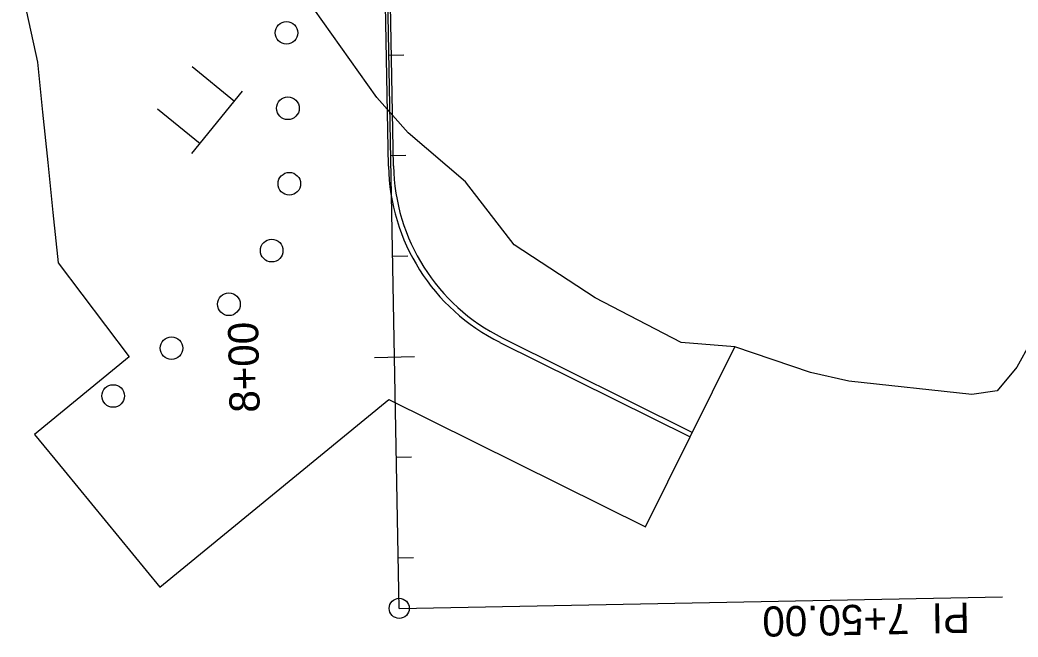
# Model space of a CAD drawing. Extents: x 1710723 to 1713003, y 548603 to 551142.
# Drawn here: x 1711666.3 to 1711864.8, y 548956.8 to 549079.5 of the extents above; entities that cross this region are included whole.
import ezdxf

# ---------------------------------------------------------------- set-up
doc = ezdxf.new("R2010")
doc.units = 0
for name, color, linetype in [('R_Horz Alg', 7, 'Continuous'), ('R_Horz Alg Annot', 7, 'Continuous'), ('R_MOT', 7, 'Continuous'), ('R_No Plot', 7, 'Continuous'), ('R_Proposed Road_Lane', 7, 'Continuous'), ('R_Striping', 7, 'Continuous')]:
    doc.layers.add(name, color=color, linetype=linetype)

msp = doc.modelspace()

# ---------------------------------------------------------------- linework, layer by layer
at = {"layer": 'R_Horz Alg'}
msp.add_line((1711741.76, 548962.46), (1711737.05, 549212.41), dxfattribs=at)
at = {"layer": 'R_Horz Alg Annot'}
for points in [[(1711742.69, 549072.5), (1711739.69, 549072.44)], [(1711743.07, 549052.5), (1711740.07, 549052.44)], [(1711743.44, 549032.5), (1711740.44, 549032.45)], [(1711736.82, 549012.38), (1711744.82, 549012.53)], [(1711744.2, 548992.51), (1711741.2, 548992.45)], [(1711744.57, 548972.51), (1711741.57, 548972.46)], [(1711741.76, 548962.46), (1711861.74, 548964.72)]]:
    msp.add_lwpolyline(points, dxfattribs=at)
msp.add_circle((1711741.76, 548962.46), 2, dxfattribs=at)
at = {"layer": 'R_MOT'}
for p, q in [((1711700.56, 549070.26), (1711709.02, 549063.36)), ((1711700.5, 549052.9), (1711710.61, 549065.3)), ((1711693.7, 549061.84), (1711702.17, 549054.94)), ((1711688.03, 549012.49), (1711669.23, 548997.07)), ((1711669.23, 548997.07), (1711675.11, 548989.89))]:
    msp.add_line(p, q, dxfattribs=at)
for points in [[(1711808.51, 549014.46), (1711797.83, 549015.34), (1711780.72, 549024.22), (1711764.61, 549034.78), (1711754.93, 549047.27), (1711743.56, 549057.03), (1711737.29, 549064.07), (1711724.77, 549081.73), (1711723.01, 549081.72), (1711718.65, 549087.89), (1711708.97, 549101.92), (1711699.3, 549115.95), (1711689.62, 549129.98), (1711679.95, 549144.01), (1711667.27, 549161.8), (1711663.44, 549166.72)], [(1711633.24, 549130.45), (1711648.31, 549110.73), (1711654.76, 549100.85), (1711661.21, 549090.97), (1711667.66, 549081.09), (1711669.8, 549071.12), (1711670.82, 549061.14), (1711671.85, 549051.16), (1711672.88, 549041.18), (1711673.91, 549031.19), (1711688.03, 549012.49)], [(1711675.11, 548989.89), (1711694.14, 548966.7), (1711739.66, 549004.03), (1711790.7, 548978.65), (1711808.51, 549014.46)]]:
    msp.add_lwpolyline(points, dxfattribs=at)
for centre in [(1711719.34, 549076.92), (1711719.62, 549061.92), (1711719.9, 549046.92), (1711716.39, 549033.61), (1711707.89, 549022.94), (1711696.46, 549014.22), (1711684.87, 549004.7)]:
    msp.add_circle(centre, 2.25, dxfattribs=at)
at = {"layer": 'R_No Plot'}
msp.add_lwpolyline([(1711869.98, 549020.25), (1711864.58, 549010.42), (1711860.69, 549005.72), (1711855.6, 549004.99), (1711831.16, 549007.62), (1711823.52, 549009.4), (1711808.51, 549014.46), (1711797.83, 549015.34), (1711780.72, 549024.22), (1711764.61, 549034.78), (1711754.93, 549047.27), (1711743.56, 549057.03), (1711737.29, 549064.07), (1711724.77, 549081.73), (1711723.01, 549081.72), (1711718.65, 549087.89), (1711708.97, 549101.92), (1711699.3, 549115.95), (1711689.62, 549129.98), (1711679.95, 549144.01), (1711667.27, 549161.8), (1711663.44, 549166.72)], dxfattribs=at)
at = {"layer": 'R_Proposed Road_Lane'}
for p, q in [((1711761.77, 549015.37), (1711799.61, 548996.56)), ((1711762.22, 549016.27), (1711800.05, 548997.45))]:
    msp.add_line(p, q, dxfattribs=at)
for radius in [39.99, 38.99]:
    msp.add_arc((1711779.59, 549051.18), radius, 181.0773, 243.5424, dxfattribs=at)
at = {"layer": 'R_Striping'}
for p, q in [((1711740.6, 549050.44), (1711740, 549082.45)), ((1711739.6, 549050.42), (1711739, 549082.43))]:
    msp.add_line(p, q, dxfattribs=at)

# ---------------------------------------------------------------- texts
at = {"layer": 'R_Horz Alg Annot'}
for s, rotation, p in [('8+00', 91.0787, (1711714.02, 549001.43)), ('PI  7+50.00', 181.0787, (1711855.17, 548963.59))]:
    msp.add_text(s, height=6, rotation=rotation, dxfattribs=at).set_placement(p)

doc.saveas('drawing.dxf')
